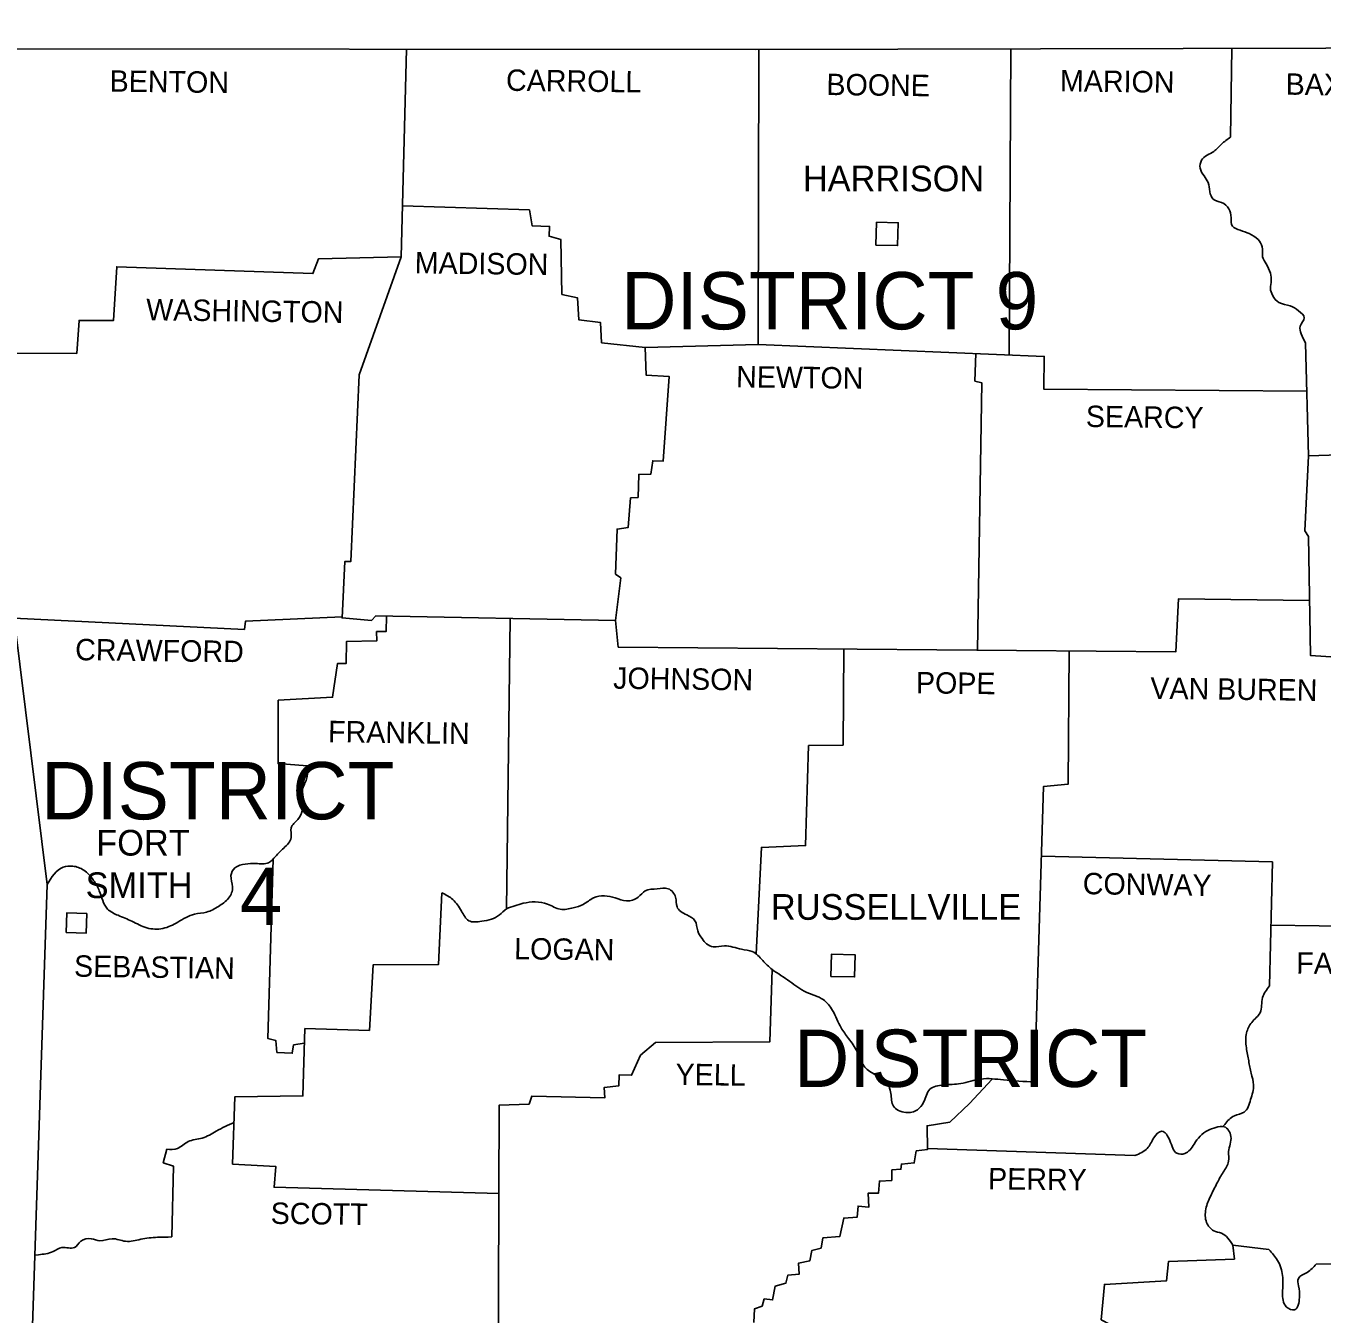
# Model space of a CAD drawing. Extents: x -0.68 to 1.92, y 0 to 0.95.
# Drawn here: x 1.1026 to 1.2203, y 0.703 to 0.8199 of the extents above; entities that cross this region are included whole.
import ezdxf

# ---------------------------------------------------------------- set-up
doc = ezdxf.new("R2010")
doc.units = 0
doc.layers.add('Default', color=7, linetype='Continuous')

msp = doc.modelspace()

# ---------------------------------------------------------------- linework, layer by layer
at = {"layer": 'Default'}
for p, q in [((1.2115, 0.7202), (1.21134, 0.72002)), ((1.10377, 0.70837), (1.10343, 0.70833))]:
    msp.add_line(p, q, dxfattribs=at)
for points in [[(1.09511, 0.81784), (1.16886, 0.81779), (1.23365, 0.81792), (1.31002, 0.81909), (1.34545, 0.81992)], [(1.09511, 0.81784), (1.10455, 0.74198), (1.10045, 0.61817)], [(1.1372, 0.81781), (1.13672, 0.79894)], [(1.13684, 0.80359), (1.14835, 0.80321), (1.14861, 0.80176), (1.15019, 0.80171), (1.15014, 0.80083), (1.1512, 0.80054), (1.1513, 0.79554), (1.15273, 0.79523), (1.15283, 0.79325), (1.15481, 0.793), (1.15491, 0.79115), (1.15886, 0.79073), (1.16912, 0.791), (1.1692, 0.81779)], [(1.19208, 0.81784), (1.19192, 0.79004)], [(1.21215, 0.81788), (1.21204, 0.80983)], [(1.23362, 0.81792), (1.23372, 0.80679), (1.23297, 0.80674), (1.23308, 0.79538), (1.22991, 0.79491), (1.23017, 0.79188), (1.23126, 0.79045), (1.23118, 0.78685), (1.22498, 0.78662), (1.22475, 0.78107), (1.2191, 0.78088), (1.21879, 0.77409), (1.21912, 0.77357), (1.21928, 0.76278), (1.229, 0.76213), (1.22887, 0.73809), (1.23665, 0.73789), (1.23665, 0.7134), (1.23053, 0.71294), (1.23009, 0.70759), (1.2198, 0.70752)], [(1.09854, 0.79022), (1.10724, 0.79019), (1.10745, 0.79318), (1.11059, 0.79318), (1.11087, 0.79805), (1.12869, 0.79743), (1.12921, 0.79878), (1.13672, 0.79894), (1.13289, 0.78825), (1.13214, 0.77131), (1.13159, 0.77129), (1.13134, 0.76618), (1.13401, 0.76595), (1.13442, 0.76636), (1.15618, 0.76595), (1.15641, 0.76353)], [(1.2191, 0.78088), (1.21884, 0.79113)], [(1.15886, 0.79073), (1.15896, 0.7882), (1.16106, 0.78809), (1.16051, 0.78042), (1.15955, 0.78044), (1.15937, 0.77922), (1.15828, 0.7792), (1.15823, 0.77712), (1.15755, 0.77707), (1.15732, 0.77437), (1.15631, 0.77424), (1.15618, 0.77015), (1.15665, 0.76981), (1.15618, 0.76595)], [(1.16912, 0.791), (1.19511, 0.78991), (1.19508, 0.78693), (1.21895, 0.78677)], [(1.18889, 0.79017), (1.18881, 0.78768), (1.18943, 0.78752), (1.18904, 0.76325)], [(1.15641, 0.76353), (1.20706, 0.76309), (1.20732, 0.76792), (1.21921, 0.76776)], [(1.10154, 0.76614), (1.12247, 0.76514), (1.12257, 0.76589), (1.13134, 0.76629)], [(1.13537, 0.76634), (1.13533, 0.76493), (1.13447, 0.76493), (1.1345, 0.7641), (1.13175, 0.76405), (1.1317, 0.76203), (1.13092, 0.76203), (1.13048, 0.75897), (1.12555, 0.75871), (1.12553, 0.75295), (1.12817, 0.75275)], [(1.14661, 0.76613), (1.14627, 0.73978)], [(1.1769, 0.76336), (1.17685, 0.75464), (1.17371, 0.75459), (1.17343, 0.74551), (1.16943, 0.74535), (1.16895, 0.73569)], [(1.19737, 0.76318), (1.19729, 0.75109), (1.19506, 0.75088), (1.19423, 0.72404)], [(1.12508, 0.74427), (1.12459, 0.728), (1.12532, 0.72782), (1.12542, 0.72673), (1.12682, 0.72666), (1.12693, 0.72741), (1.12792, 0.72757)], [(1.19486, 0.74455), (1.21583, 0.74403), (1.21557, 0.73278)], [(1.14041, 0.74123), (1.1401, 0.73472), (1.13416, 0.73467), (1.13382, 0.72873), (1.12796, 0.72889), (1.12778, 0.72279), (1.12161, 0.72271), (1.1214, 0.71659), (1.12532, 0.71639), (1.12516, 0.71449), (1.14558, 0.71393)], [(1.2157, 0.7383), (1.22887, 0.73809)], [(1.17039, 0.73425), (1.17018, 0.72769), (1.15981, 0.72764), (1.15844, 0.72647), (1.15763, 0.72466), (1.15652, 0.72471), (1.15647, 0.7237), (1.15514, 0.72354), (1.15519, 0.72261), (1.14858, 0.72277), (1.14832, 0.72204), (1.1456, 0.72194), (1.14558, 0.71393)], [(1.19037, 0.7243), (1.18831, 0.72209), (1.18655, 0.72041), (1.18447, 0.72007), (1.1845, 0.71792), (1.18349, 0.71779), (1.18331, 0.7167), (1.18214, 0.71659), (1.18209, 0.71613), (1.18128, 0.71607), (1.18126, 0.71511), (1.18014, 0.71506), (1.18007, 0.71397), (1.17913, 0.71397), (1.17918, 0.71268), (1.1782, 0.71278), (1.17812, 0.71177), (1.1769, 0.71169), (1.17656, 0.71003), (1.17501, 0.7099), (1.17485, 0.70897), (1.17402, 0.70876), (1.17382, 0.7078), (1.17278, 0.70759), (1.17286, 0.70661), (1.17182, 0.7065), (1.17164, 0.70578), (1.17068, 0.70552), (1.17044, 0.70427), (1.16969, 0.70435), (1.16948, 0.7037), (1.16881, 0.70347), (1.16873, 0.70223)], [(1.11588, 0.70998), (1.11603, 0.71641), (1.1151, 0.71672), (1.11541, 0.71794)], [(1.20335, 0.71737), (1.1845, 0.718)], [(1.14558, 0.71393), (1.14552, 0.69525), (1.14321, 0.6952), (1.14342, 0.69385), (1.14122, 0.69387), (1.14116, 0.69286), (1.13901, 0.69286), (1.13906, 0.69216), (1.1359, 0.69206), (1.13582, 0.68928), (1.13274, 0.68957), (1.13222, 0.66711)], [(1.21552, 0.70884), (1.21225, 0.70923), (1.21238, 0.70798), (1.20639, 0.70775), (1.20621, 0.70599), (1.20058, 0.70567), (1.20027, 0.70246), (1.2011, 0.70204), (1.2011, 0.69994)]]:
    msp.add_lwpolyline(points, dxfattribs=at)
for points in [[(1.17983, 0.80002), (1.17988, 0.8021), (1.18186, 0.80205), (1.1818, 0.79997)], [(1.10628, 0.73763), (1.10633, 0.73939), (1.10815, 0.73934), (1.1081, 0.73757)], [(1.17573, 0.73363), (1.17579, 0.73565), (1.17794, 0.7356), (1.17789, 0.73358)]]:
    msp.add_lwpolyline(points, close=True, dxfattribs=at)
for points in [[(1.21204, 0.80983), (1.21121, 0.80918), (1.21051, 0.80853), (1.2094, 0.80773), (1.20927, 0.807), (1.20963, 0.8063), (1.20999, 0.8057), (1.21015, 0.80487), (1.21046, 0.8042), (1.21121, 0.80389), (1.21189, 0.80332), (1.21209, 0.80251), (1.2122, 0.80174), (1.2129, 0.80137), (1.21373, 0.80106), (1.21453, 0.80052), (1.2149, 0.79987), (1.21495, 0.79896), (1.21528, 0.79831), (1.21565, 0.79746), (1.21573, 0.79678), (1.21565, 0.79611), (1.21585, 0.79546), (1.21643, 0.79481), (1.21746, 0.7945), (1.21821, 0.79406), (1.21873, 0.79341), (1.21837, 0.79266), (1.21845, 0.79196), (1.21884, 0.79113)], [(1.12817, 0.75275), (1.12817, 0.75179), (1.12781, 0.7508), (1.12757, 0.74992), (1.12773, 0.74878), (1.12732, 0.74787), (1.12672, 0.74712), (1.12672, 0.74624), (1.12604, 0.74528), (1.12529, 0.74452), (1.12467, 0.74395), (1.1235, 0.74388), (1.12254, 0.74382), (1.12161, 0.74349), (1.12125, 0.74279), (1.1214, 0.74175), (1.12104, 0.74074), (1.12011, 0.73999), (1.11904, 0.73947), (1.11795, 0.73929), (1.11642, 0.73856), (1.11507, 0.73799), (1.1136, 0.73804), (1.11225, 0.73864), (1.111, 0.73918), (1.11004, 0.73975), (1.10929, 0.74141), (1.10877, 0.74235), (1.10789, 0.74328), (1.10688, 0.74364), (1.106, 0.74354), (1.10455, 0.74198)], [(1.14627, 0.73978), (1.1478, 0.74027), (1.14889, 0.7404), (1.15001, 0.74019), (1.15115, 0.73973), (1.15234, 0.73986), (1.15325, 0.74017), (1.15418, 0.74076), (1.15517, 0.74095), (1.15615, 0.74076), (1.15717, 0.74048), (1.15823, 0.74082), (1.15888, 0.74139), (1.15997, 0.74159), (1.16095, 0.74159), (1.16163, 0.74082), (1.16176, 0.73996), (1.16264, 0.73921), (1.16339, 0.73869), (1.16365, 0.73776), (1.16404, 0.73706), (1.16445, 0.73659), (1.16505, 0.73633), (1.16606, 0.73641), (1.16762, 0.7361), (1.1686, 0.73589), (1.16954, 0.73508), (1.17039, 0.73425)], [(1.14041, 0.74123), (1.1414, 0.74061), (1.14218, 0.73957), (1.14285, 0.73869), (1.14402, 0.73864), (1.14492, 0.73882), (1.14627, 0.73978)], [(1.17039, 0.73425), (1.172, 0.73317), (1.1735, 0.73221), (1.17503, 0.73153), (1.17589, 0.73055), (1.17667, 0.72896), (1.17734, 0.728), (1.17812, 0.72681), (1.17874, 0.72551), (1.17968, 0.72476), (1.18069, 0.72414), (1.18118, 0.723), (1.18141, 0.72186), (1.18253, 0.72129), (1.18359, 0.72152), (1.18416, 0.72222), (1.18473, 0.72339), (1.18595, 0.72378), (1.18753, 0.72391), (1.18935, 0.72432), (1.1914, 0.72424), (1.19423, 0.72404)], [(1.21557, 0.73278), (1.21495, 0.73171), (1.21471, 0.73034), (1.21396, 0.72946), (1.21349, 0.7285), (1.21347, 0.72715), (1.21368, 0.72596), (1.21391, 0.72484), (1.21412, 0.72378), (1.21386, 0.72245), (1.21326, 0.72131), (1.21238, 0.72098), (1.2115, 0.7202)], [(1.11541, 0.71794), (1.1164, 0.71802), (1.11736, 0.71864), (1.11863, 0.71895), (1.11992, 0.7196), (1.12153, 0.72037)], [(1.20335, 0.71737), (1.20447, 0.71802), (1.20507, 0.71898), (1.20579, 0.71958), (1.20652, 0.71875), (1.20717, 0.71758), (1.20787, 0.71755), (1.20872, 0.71841), (1.20927, 0.71913), (1.20997, 0.71965), (1.21069, 0.71991), (1.21145, 0.71999), (1.21207, 0.71911), (1.21186, 0.71773), (1.21186, 0.71685), (1.21137, 0.71587), (1.2108, 0.71486), (1.21023, 0.71371), (1.20979, 0.71252), (1.20986, 0.7113), (1.21051, 0.71055), (1.21121, 0.71032), (1.21225, 0.70923)], [(1.11588, 0.70998), (1.11458, 0.70995), (1.11305, 0.70977), (1.11168, 0.70959), (1.11046, 0.70982), (1.10934, 0.70964), (1.10856, 0.70982), (1.10761, 0.70959), (1.10703, 0.70902), (1.10589, 0.70902), (1.10509, 0.70866), (1.10377, 0.70837)], [(1.21552, 0.70884), (1.2163, 0.70785), (1.21676, 0.70648), (1.21676, 0.70492), (1.2171, 0.70365), (1.21785, 0.70337), (1.21829, 0.70448), (1.21821, 0.70555), (1.21819, 0.70622), (1.21899, 0.70676), (1.2198, 0.70752)]]:
    msp.add_spline(points, degree=3, dxfattribs=at)

# ---------------------------------------------------------------- texts
for s, rotation, p in [('BENTON', 359.2874, (1.11022, 0.81395)), ('CARROLL', 359.267, (1.14622, 0.81403)), ('MARION', 359.2237, (1.19653, 0.81398)), ('BOONE', 359.3139, (1.17532, 0.81364)), ('BAXTER', 359.2892, (1.21703, 0.81367)), ('MADISON', 359.217, (1.13793, 0.79746)), ('WASHINGTON', 359.2079, (1.11354, 0.7932)), ('NEWTON', 359.303, (1.16712, 0.78711)), ('SEARCY', 359.2838, (1.19888, 0.78351)), ('CRAWFORD', 359.2748, (1.10709, 0.76234)), ('JOHNSON', 359.2575, (1.15595, 0.75975)), ('POPE', 359.3389, (1.18345, 0.75933)), ('VAN BUREN', 359.2547, (1.20474, 0.75884)), ('FRANKLIN', 359.1782, (1.13006, 0.7549)), ('CONWAY', 359.1737, (1.1986, 0.7411)), ('LOGAN', 359.3076, (1.14696, 0.73519)), ('FAULKNER', 359.2447, (1.21799, 0.73389)), ('SEBASTIAN', 359.1959, (1.10699, 0.73361)), ('YELL', 359.3097, (1.16162, 0.72378)), ('PERRY', 359.2992, (1.19, 0.71431)), ('SCOTT', 359.32, (1.12485, 0.71117))]:
    msp.add_text(s, height=0.001945, rotation=rotation, dxfattribs=at).set_placement(p)
for s, height, p in [('HARRISON', 0.002334, (1.17319, 0.8049)), ('DISTRICT 9', 0.005203, (1.15669, 0.79237)), ('DISTRICT', 0.005203, (1.10401, 0.74789)), ('FORT', 0.002334, (1.10901, 0.7446)), ('SMITH', 0.002334, (1.10805, 0.74074)), ('4', 0.0052, (1.12205, 0.73831)), ('RUSSELLVILLE', 0.0023341, (1.17029, 0.73877)), ('DISTRICT', 0.005203, (1.17238, 0.7236))]:
    msp.add_text(s, height=height, dxfattribs=at).set_placement(p)

doc.saveas('drawing.dxf')
